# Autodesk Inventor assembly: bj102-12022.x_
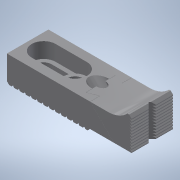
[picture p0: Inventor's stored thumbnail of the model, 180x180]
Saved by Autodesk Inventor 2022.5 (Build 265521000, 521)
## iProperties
Part Number: bj102-12022.x_
Material: 一般
Document SubType Name: Assembly
Designer: ImaoCorp
Sending System: SOLIDWORKS 2017-2017317
MC: AMD64
MC_MODEL: Intel64 Family 6 Model 60 Stepping 3, GenuineIntel
OS: Windows_NT
FRU: Parasolid Version 29.0, build 201,  4-17-2017
FORMAT: text
GUISE: transmit
KEY: bj102-12022
FILE: bj102-12022.x_t
DATE: Fri Mar 15 10:32:34 2019
Author: ImaoCorp
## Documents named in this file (4)
- X:\14_SW2022-Inv2022\00_全2023-1023新製品(TCC)まで\b\bj102-12022\BJ102-12022.iam
- X:\14_SW2022-Inv2022\00_全2023-1023新製品(TCC)まで\b\bj102-12022\bj102-12022_01.ipt
- X:\14_SW2022-Inv2022\00_全2023-1023新製品(TCC)まで\b\bj102-12022\bj102-12022_02.ipt
- X:\14_SW2022-Inv2022\00_全2023-1023新製品(TCC)まで\b\bj102-12022\bj102-12022_03.ipt
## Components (3 placed, 3 different names)
1. bj102-12022_01
2. bj102-12022_02
3. bj102-12022_03
